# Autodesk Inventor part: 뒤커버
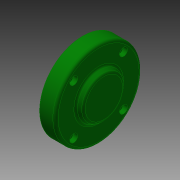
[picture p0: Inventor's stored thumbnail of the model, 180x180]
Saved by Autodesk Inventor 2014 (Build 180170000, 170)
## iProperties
Company: 한국ATC센터
Created: 2015-12
Part Number: 뒤커버
Document SubType Name: Modeling
Designer: mdu
Density: 2.71 g/cm^3
Mass: 105.756 g
Surface Area: 115.002 cm^2
Volume: 39.0244 cm^3
Material: 알루미늄 6061
Appearance: 진녹색
Author: mdu
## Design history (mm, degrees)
sketch "스케치1"
  geometry: L1 (-10.5, 0)-(10.5, 0); L2 (10.5, 0)-(10.5, 22.5); L3 (10.5, 22.5)-(5.5, 22.5); L4 (5.5, 22.5)-(5.5, 32.5); L5 (5.5, 32.5)-(-6.5, 32.5); L6 (-6.5, 32.5)-(-6.5, 17.5); L7 (-6.5, 17.5)-(-10.5, 15.191); L8 (-10.5, 15.191)-(-10.5, 0); 2 further points
  constraints: 16 end point, 3 parallel, 3 perpendicular, 1 coincident, 1 horizontal, 1 midpoint
  dimensions: "d0" = 21 distance of L1.start L1.end; "d1" = 65 diameter of L5 L1; "d2" = 45 diameter of L3 L1; "d3" = 35 diameter of L6.end L1; "d4" = 120 deg angle of L7 L6; "d5" = 12 distance of L4.end L5.end; "d6" = 5 distance of L2.end L3.end
revolve "회전1" sketch "스케치1" stored, may be unused: angle "d7" = 90 deg
sketch "스케치2"
  geometry: L1 (0, 0)-(32.5, 0); L2 (0, 0)-(18.738, 18.738); 1 further point
  constraints: 4 end point, 1 horizontal, 1 horizontal alignment, 1 other
  dimensions: "d8" = 45 deg angle of L1 L2; "d9" = 26.5 distance of L1.start L2.end
hole "구멍1" sketch "스케치2" at (18.738, 18.738) diameter "d10" = 3.4; stored, may be unused: countersink angle "d14" = 90 deg, drill point angle "d16" = 118 deg; dims "d11" = 6, "d12" = 6, "d13" = 3.3, "d15" = 8
fillet "모깎기1" dims "d20" = 2
hole "구멍2" diameter "d23" = 15; stored, may be unused: countersink angle "d27" = 90 deg, drill point angle "d29" = 0 deg; dims "d21" = 10, "d22" = 10, "d24" = 6, "d25" = 35, "d26" = 11, "d28" = 14
chamfer "모따기1" distance "d39" = 1; stored, may be unused: second distance "d40" = 2, angle "d41" = 45 deg
fillet "모깎기2" dims "d42" = 0.3
chamfer "모따기3" distance "d57" = 1; stored, may be unused: second distance "d58" = 2, angle "d59" = 45 deg
fillet "모깎기4" dims "d60" = 1
node "솔리드1"
pattern_circular "원형 패턴1" dims angle "d18" = 360 deg
